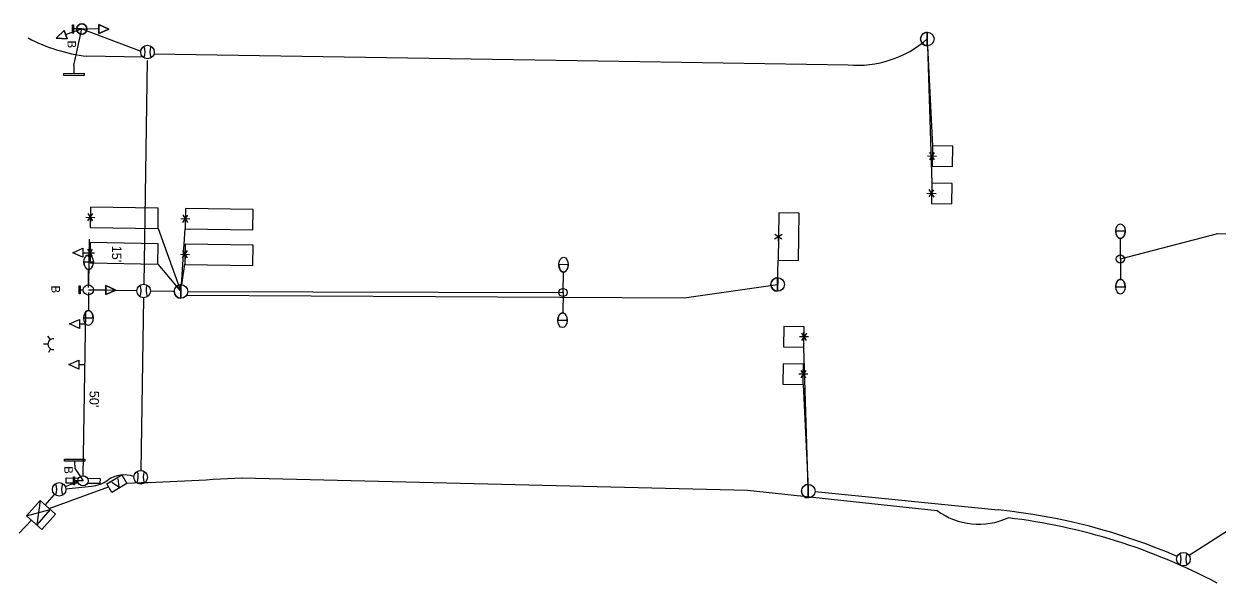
# Model space of a CAD drawing. Extents: x 596176 to 605330, y 332416 to 402398.
# Drawn here: x 602165.4 to 602517.5, y 366045.6 to 366210.7 of the extents above; entities that cross this region are included whole.
import ezdxf

# ---------------------------------------------------------------- set-up
doc = ezdxf.new("R2010")
doc.units = 0
for name, color, linetype in [('P_LTG', 7, 'Continuous'), ('P_SIG', 7, 'Continuous'), ('P_SIG_Bold', 7, 'Continuous'), ('P_SIG_Conduit', 7, 'Continuous'), ('P_SIG_IC', 7, 'Continuous'), ('P_SIG_Loops', 7, 'Continuous')]:
    doc.layers.add(name, color=color, linetype=linetype)

# ---------------------------------------------------------------- blocks, each defined once
blk = doc.blocks.new('_U342')
at = {"layer": 'P_LTG'}
for p, q in [((4.3, 25), (-4.2, 25)), ((0, 0), (0, 18.5)), ((0, 0), (0, -18.3)), ((-4.3, -25), (4.2, -25))]:
    blk.add_line(p, q, dxfattribs=at)
blk.add_circle((0, 0), 3.68, dxfattribs=at)
for centre, major_axis in [((0, 25), (0, 6.65)), ((0, -25), (0, -6.65))]:
    blk.add_ellipse(centre, major_axis=major_axis, ratio=0.636439, dxfattribs=at)
for centre, major_axis in [((0, 25), (0, 6.65)), ((0, -25), (0, -6.65))]:
    blk.add_ellipse(centre, major_axis=major_axis, ratio=0.636439, start_param=1.570796, end_param=4.712389, dxfattribs=at)

msp = doc.modelspace()

# ---------------------------------------------------------------- linework, layer by layer
at = {"layer": 'P_LTG'}
for p, q in [((602185.95, 366140.35), (602183.17, 366140.35)), ((602184.55, 366132.87), (602184.55, 366138.16)), ((602326.06, 366139.56), (602323.29, 366139.61)), ((602324.53, 366131.39), (602324.63, 366137.39)), ((602184.52, 366131.36), (602184.52, 366126.06)), ((602324.53, 366131.39), (602324.44, 366125.32)), ((602183.11, 366123.87), (602185.89, 366123.87)), ((602323, 366123.21), (602325.78, 366123.17))]:
    msp.add_line(p, q, dxfattribs=at)
msp.add_circle((602324.53, 366131.38), 1.21, dxfattribs=at)
for centre, major_axis in [((602184.56, 366140.35), (0, 2.18)), ((602324.68, 366139.59), (0.03, 2.18)), ((602184.5, 366123.87), (0, -2.18)), ((602324.39, 366123.19), (-0.03, -2.18))]:
    msp.add_ellipse(centre, major_axis=major_axis, ratio=0.636439, dxfattribs=at)
for centre, major_axis in [((602184.56, 366140.35), (0, 2.18)), ((602324.68, 366139.59), (0.03, 2.18)), ((602184.5, 366123.87), (0, -2.18)), ((602324.39, 366123.19), (-0.03, -2.18))]:
    msp.add_ellipse(centre, major_axis=major_axis, ratio=0.636439, start_param=1.570796, end_param=4.712389, dxfattribs=at)
at = {"layer": 'P_SIG'}
for p, q in [((602177.77, 366207.48), (602182.54, 366209.15)), ((602182.58, 366209.15), (602180.08, 366209.15)), ((602180.15, 366198.33), (602182.58, 366209.15)), ((602187.6, 366209.14), (602182.54, 366209.15)), ((602432, 366208.2), (602431.98, 366204.2)), ((602180.15, 366198.33), (602180.15, 366195.93)), ((602182.87, 366143.13), (602184.64, 366143.13)), ((602211.79, 366133.68), (602211.77, 366129.68)), ((602387.85, 366135.75), (602387.83, 366131.75)), ((602183.06, 366132.11), (602181.53, 366132.11)), ((602189.59, 366132.1), (602184.53, 366132.11)), ((602181.86, 366122.12), (602183.63, 366122.12)), ((602172.51, 366116.1), (602171.28, 366116.1)), ((602173.35, 366117.52), (602172.47, 366118.51)), ((602173.33, 366114.73), (602172.74, 366113.65)), ((602181.67, 366110.12), (602183.44, 366110.12)), ((602180.53, 366079.34), (602180.51, 366081.74)), ((602180.53, 366079.34), (602182.89, 366075.82)), ((602182.89, 366075.82), (602180.39, 366075.82)), ((602191.42, 366075.36), (602193.42, 366074.02)), ((602193.21, 366076.42), (602193.42, 366074.02)), ((602396.88, 366074.74), (602396.86, 366070.74)), ((602166.26, 366065.43), (602170.21, 366069.95)), ((602166.26, 366065.43), (602170.21, 366069.95)), ((602170.21, 366069.95), (602169.28, 366062.8)), ((602170.21, 366069.95), (602169.28, 366062.8)), ((602170.21, 366069.95), (602174.73, 366066)), ((602170.21, 366069.95), (602174.73, 366066)), ((602166.26, 366065.43), (602173.22, 366067.32)), ((602166.26, 366065.43), (602173.22, 366067.32)), ((602173.22, 366067.32), (602169.28, 366062.8)), ((602173.22, 366067.32), (602169.28, 366062.8)), ((602170.78, 366061.48), (602166.26, 366065.43)), ((602170.78, 366061.48), (602166.26, 366065.43)), ((602174.73, 366066), (602170.78, 366061.48)), ((602174.73, 366066), (602170.78, 366061.48))]:
    msp.add_line(p, q, dxfattribs=at)
for points in [[(602190.56, 366209.14), (602187.6, 366207.82), (602187.6, 366210.46), (602190.56, 366209.14)], [(602187.6, 366207.82), (602190.56, 366209.14), (602187.6, 366210.46), (602187.6, 366207.82)], [(602174.98, 366206.49), (602177.33, 366208.72), (602178.21, 366206.23), (602174.98, 366206.49)], [(602174.98, 366206.49), (602177.33, 366208.72), (602178.21, 366206.23), (602174.98, 366206.49)], [(602177.33, 366208.72), (602174.98, 366206.49), (602178.21, 366206.23), (602177.33, 366208.72)], [(602431.98, 366204.2), (602432, 366208.2)], [(602192.55, 366132.1), (602189.59, 366130.78), (602189.59, 366133.42), (602192.55, 366132.1)], [(602192.55, 366132.1), (602189.59, 366130.78), (602189.59, 366133.42), (602192.55, 366132.1)], [(602189.59, 366130.78), (602192.55, 366132.1), (602189.59, 366133.42), (602189.59, 366130.78)], [(602211.77, 366129.68), (602211.79, 366133.68)], [(602387.83, 366131.75), (602387.85, 366135.75)], [(602396.86, 366070.74), (602396.88, 366074.74)]]:
    msp.add_lwpolyline(points, dxfattribs=at)
for points in [[(602180.08, 366210.35), (602180.08, 366207.95), (602179.75, 366207.95), (602179.75, 366210.35)], [(602177.19, 366196.06), (602183.19, 366196.07), (602183.19, 366195.47), (602177.19, 366195.47)], [(602179.91, 366143.13), (602182.87, 366144.45), (602182.87, 366141.82)], [(602182.03, 366133.38), (602182.03, 366130.98), (602181.71, 366130.98), (602181.71, 366133.38)], [(602178.9, 366122.12), (602181.86, 366123.44), (602181.86, 366120.8)], [(602178.71, 366110.12), (602181.67, 366111.44), (602181.67, 366108.8)], [(602183.47, 366081.64), (602177.47, 366081.58), (602177.46, 366082.18), (602183.46, 366082.24)], [(602180.4, 366077.02), (602180.4, 366074.62), (602180.07, 366074.62), (602180.07, 366077.02)], [(602189.9, 366074.89), (602194.39, 366077.55), (602195.87, 366075.04), (602191.38, 366072.38)]]:
    msp.add_lwpolyline(points, close=True, dxfattribs=at)
for centre, radius in [((602182.54, 366209.15), 1.52), ((602182.54, 366209.15), 1.52), ((602182.54, 366209.15), 1.52), ((602431.99, 366206.2), 2), ((602201.91, 366202.35), 2), ((602200.78, 366131.85), 2), ((602211.78, 366131.68), 2), ((602387.84, 366133.75), 2), ((602199.91, 366076.86), 2), ((602175.85, 366073.28), 2), ((602396.87, 366072.74), 2), ((602507.57, 366052.68), 2)]:
    msp.add_circle(centre, radius, dxfattribs=at)
for centre, radius, start, end in [((602182.54, 366209.15), 1.52, 0, 180), ((602182.54, 366209.15), 1.52, 180, 0), ((602431.99, 366206.2), 2, 89.7008, 180), ((602196.84, 366202.38), 4.36, 336.6741, 22.5272), ((602206.98, 366202.39), 4.36, 157.5751, 203.4282), ((602431.99, 366206.2), 2, 180, 269.7008), ((602195.71, 366131.89), 4.36, 336.6741, 22.5272), ((602205.85, 366131.9), 4.36, 157.5751, 203.4282), ((602211.78, 366131.68), 2, 89.7008, 180), ((602387.84, 366133.75), 2, 89.7008, 180), ((602387.84, 366133.75), 2, 180, 269.7008), ((602211.78, 366131.68), 2, 180, 269.7008), ((602174.09, 366116.12), 1.58, 82.4034, 277.9109), ((602194.84, 366076.89), 4.36, 336.6741, 22.5272), ((602204.98, 366076.9), 4.36, 157.5751, 203.4282), ((602170.78, 366073.31), 4.36, 336.6741, 22.5272), ((602180.92, 366073.32), 4.36, 157.5751, 203.4282), ((602396.87, 366072.74), 2, 89.7008, 180), ((602396.87, 366072.74), 2, 180, 269.7008), ((602502.5, 366052.71), 4.36, 336.6741, 22.5272), ((602512.64, 366052.72), 4.36, 157.5751, 203.4282)]:
    msp.add_arc(centre, radius, start, end, dxfattribs=at)
at = {"layer": 'P_SIG_Bold'}
for p, q in [((602184.7, 366147.12), (602184.49, 366133.63)), ((602182.92, 366077.32), (602183.69, 366125.81))]:
    msp.add_line(p, q, dxfattribs=at)
for points in [[(602181.58, 366075.09), (602177.88, 366075.15), (602177.91, 366076.64), (602181.61, 366076.59)], [(602184.21, 366076.55), (602187.91, 366076.49), (602187.88, 366074.99), (602184.18, 366075.05)]]:
    msp.add_lwpolyline(points, dxfattribs=at)
for centre in [(602184.46, 366132.13), (602182.89, 366075.82)]:
    msp.add_circle(centre, 1.5, dxfattribs=at)
at = {"layer": 'P_SIG_Conduit'}
for p, q in [((602182.58, 366209.15), (602199.92, 366202.59)), ((602201.86, 366199.84), (602200.82, 366133.85)), ((602198.78, 366131.88), (602186.06, 366132.05)), ((602200.75, 366129.85), (602199.94, 366078.85)), ((602209.78, 366131.7), (602202.78, 366131.8)), ((602560.08, 366086.45), (602509.25, 366053.76)), ((602181.3, 366075.65), (602177.69, 366074.07)), ((602171.73, 366068.62), (602174.53, 366071.78)), ((602164.01, 366060.34), (602167.68, 366064.2))]:
    msp.add_line(p, q, dxfattribs=at)
for points in [[(602200.57, 366200.86), (602184.03, 366201.13)], [(602203.83, 366201.81), (602334.87, 366199.73)], [(602334.87, 366199.73), (602408.63, 366198.56)], [(602488.97, 366141.28), (602517.76, 366148.83), (602560.09, 366148.16)], [(602213.49, 366130.64), (602360.3, 366129.82), (602387.84, 366133.71)], [(602213.78, 366131.64), (602324.53, 366131.39)], [(602177.84, 366073.47), (602185.4, 366074.22)], [(602398.87, 366072.65), (602452.92, 366067.21)]]:
    msp.add_lwpolyline(points, dxfattribs=at)
for centre, radius, start, end in [((602189.28, 366248.4), 47.56, 241.6848, 263.6691), ((602411.3, 366229.96), 31.51, 265.1371, 311.0512), ((602195.02, 366069.35), 8.22, 69.375, 125.594), ((602184.42, 366084.17), 10, 275.628, 305.594), ((602435.07, 365890.1), 178, 66.6104, 84.2457)]:
    msp.add_arc(centre, radius, start, end, dxfattribs=at)
at = {"layer": 'P_SIG_IC'}
for points in [[(602229.8, 366076.68), (602378.97, 366073.09), (602434.86, 366067.02)], [(602172.92, 366067.59), (602190.4, 366074.05)]]:
    msp.add_lwpolyline(points, dxfattribs=at)
for centre, radius, start, end in [((602107.38, 368311.81), 2238.47, 272.2651, 273.13521), ((602447.21, 366084.04), 21.02, 234.0569, 294.2813), ((602435.07, 365890.1), 176, 62.0698, 83.2199)]:
    msp.add_arc(centre, radius, start, end, dxfattribs=at)
at = {"layer": 'P_SIG_Loops'}
for p, q in [((602432.05, 366204.2), (602433.32, 366163.67)), ((602432.08, 366204.2), (602433.49, 366174.67)), ((602432.71, 366170.57), (602434.15, 366172.72)), ((602434.16, 366170.56), (602432.76, 366172.76)), ((602432.07, 366171.67), (602434.75, 366171.63)), ((602433.44, 366171.67), (602433.4, 366168.67)), ((602432.53, 366159.57), (602433.97, 366161.72)), ((602433.99, 366159.56), (602432.59, 366161.76)), ((602431.9, 366160.67), (602434.58, 366160.63)), ((602433.27, 366160.67), (602433.22, 366157.67)), ((602184.33, 366152.51), (602185.77, 366154.66)), ((602185.78, 366152.5), (602184.39, 366154.69)), ((602212.34, 366152.08), (602213.79, 366154.23)), ((602213.8, 366152.07), (602212.4, 366154.26)), ((602391.17, 366154.83), (602388.17, 366154.88)), ((602183.69, 366153.6), (602186.37, 366153.56)), ((602185.07, 366153.6), (602185.02, 366150.6)), ((602211.71, 366153.18), (602214.39, 366153.14)), ((602213.08, 366153.17), (602213.04, 366150.17)), ((602205.02, 366150.28), (602211.78, 366131.67)), ((602211.92, 366133.67), (602213.05, 366150.17)), ((602386.96, 366147.18), (602389.15, 366148.58)), ((602386.97, 366148.64), (602389.12, 366147.2)), ((602388.07, 366149.27), (602388.02, 366146.59)), ((602184.27, 366142.01), (602185.71, 366144.16)), ((602185.72, 366142), (602184.32, 366144.19)), ((602212.28, 366141.58), (602213.72, 366143.73)), ((602213.73, 366141.57), (602212.34, 366143.76)), ((602183.63, 366143.1), (602186.31, 366143.06)), ((602185, 366143.1), (602184.96, 366140.1)), ((602211.64, 366142.68), (602214.32, 366142.64)), ((602213.02, 366142.67), (602212.97, 366139.67)), ((602387.84, 366133.75), (602387.95, 366140.88)), ((602204.95, 366139.78), (602211.78, 366131.67)), ((602212.07, 366133.66), (602212.95, 366139.71)), ((602394.88, 366119.38), (602396.28, 366117.18)), ((602396.34, 366119.37), (602394.89, 366117.22)), ((602395.6, 366118.27), (602395.65, 366121.27)), ((602396.97, 366118.27), (602394.29, 366118.31)), ((602396.89, 366073.73), (602395.55, 366115.27)), ((602394.7, 366108.36), (602396.1, 366106.17)), ((602396.16, 366108.35), (602394.71, 366106.2)), ((602395.42, 366107.26), (602395.47, 366110.26)), ((602396.79, 366107.26), (602394.11, 366107.3)), ((602395.37, 366104.26), (602396.89, 366073.73))]:
    msp.add_line(p, q, dxfattribs=at)
for points in [[(602433.4, 366168.67), (602439.4, 366168.57), (602439.49, 366174.57), (602433.49, 366174.67)], [(602433.22, 366157.67), (602439.22, 366157.57), (602439.32, 366163.57), (602433.32, 366163.67)], [(602185.02, 366150.6), (602205.02, 366150.28), (602205.11, 366156.28), (602185.11, 366156.6)], [(602213.04, 366150.17), (602233.03, 366149.86), (602233.13, 366155.86), (602213.13, 366156.17)], [(602388.17, 366154.88), (602387.95, 366140.88), (602393.95, 366140.79), (602394.17, 366154.79)], [(602184.96, 366140.1), (602204.95, 366139.78), (602205.05, 366145.78), (602185.05, 366146.1)], [(602212.97, 366139.67), (602232.97, 366139.36), (602233.06, 366145.36), (602213.06, 366145.67)], [(602395.65, 366121.27), (602389.65, 366121.37), (602389.55, 366115.37), (602395.55, 366115.27)], [(602395.47, 366110.26), (602389.47, 366110.36), (602389.37, 366104.36), (602395.37, 366104.26)]]:
    msp.add_lwpolyline(points, close=True, dxfattribs=at)

# ---------------------------------------------------------------- block references
at = {"layer": 'P_LTG', "xscale": 0.32808333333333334, "yscale": 0.32808333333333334}
msp.add_blockref('_U342', (602488.97, 366141.28), dxfattribs=at)

# ---------------------------------------------------------------- texts
at = {"layer": 'P_SIG'}
for s, height, rotation, p in [('B', 2.52, 270, (602178.33, 366205.74)), ('B', 2.52, 270, (602173.58, 366133.43)), ("50'", 2.8, 269.0919, (602184.84, 366102.4)), ('B', 2.52, 270, (602177.36, 366080.11))]:
    msp.add_text(s, height=height, rotation=rotation, dxfattribs=at).set_placement(p)
at = {"layer": 'P_SIG_Bold'}
msp.add_text("15'", height=2.8, rotation=269.0919, dxfattribs=at).set_placement((602191.48, 366145.23))

doc.saveas('drawing.dxf')
